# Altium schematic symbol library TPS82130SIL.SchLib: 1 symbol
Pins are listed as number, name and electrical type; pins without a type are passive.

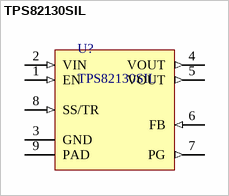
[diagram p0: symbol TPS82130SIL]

## TPS82130SIL
designator U?
footprint SIL0008C
pins: 1 EN (in), 2 VIN (in), 3 GND (power), 4 VOUT (out), 5 VOUT (out), 6 FB (in), 7 PG (out), 8 SS/TR (in), 9 PAD (power)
